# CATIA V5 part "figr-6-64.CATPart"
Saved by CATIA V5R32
Part number: Part1
Bounding box of the stored display mesh (mm): x -50.648 to 96.836, y -72.183 to 72.183, z -40 to 40
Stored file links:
  D:\PROJECTS\Project 2022\CATIA V5 6R 2022\Resources\Part Files\c06_catia_v5_6r2022_prt\figr-6-64.CATPart
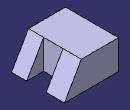
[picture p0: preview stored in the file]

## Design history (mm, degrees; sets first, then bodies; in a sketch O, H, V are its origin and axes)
Set1
  Plane1: type Offset, RefPlane face of Pad1, Offset -50, reversed
  Plane2: type Offset, RefPlane Plane1, Offset 53
Body1 (main body)
  Sketch1 on xy-plane, origin (0, 0, 0), H (1, 0, 0), V (0, 1, 0)
    line L1 (-50.6478, 72.1832) -> (50.6478, 72.1832)
    line L2 (50.6478, 72.1832) -> (50.6478, -72.1832)
    line L3 (50.6478, -72.1832) -> (-50.6478, -72.1832)
    line L4 (-50.6478, -72.1832) -> (-50.6478, 72.1832)
    axis line L5 (50.6478, -72.1832) -> (-50.6478, 72.1832)
    horizontal: L1 H, L3 H
    vertical: L2 V, L4 V
    midpoint: O L5
  Pad1: profile Sketch1, direction (0, 0, 1), length 40, mirrored extent
  Draft1: Angle 30, Neutral face of Pad1, PullDir (0, 0, 1), SupportToDraft face of Pad1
